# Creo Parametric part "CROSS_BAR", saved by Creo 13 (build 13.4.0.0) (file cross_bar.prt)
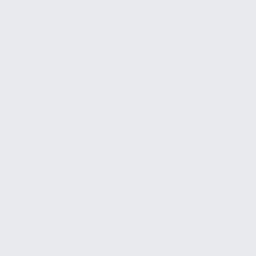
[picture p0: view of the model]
Units: millimeter Newton Second (mmNs); MM, TONNE, SECS

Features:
  1. datum plane "RIGHT"
  2. datum plane "TOP"
  3. datum plane "FRONT"
  4. coordinate system
  5. protrusion
  6. cut
  7. cut

Surfaces: 8 plane, 2 cylinder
